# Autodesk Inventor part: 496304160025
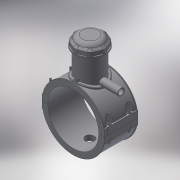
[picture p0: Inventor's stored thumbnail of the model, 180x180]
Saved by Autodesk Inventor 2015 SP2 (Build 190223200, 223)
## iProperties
Created: 2017-07
Part Number: 496304160025
Material: Generic
Description: PLASSON TAPPING SADDLE 160x25
Document SubType Name: Modeling
Designer: KIM
Mass: 1390.11 g
Surface Area: 2382.65 cm^2
Volume: 1390.11 cm^3
Density: 1 g/cm^3
Appearance: Default
Author: KIM
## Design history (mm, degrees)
derived "496304.ipt"
feature "Solid1::496304.ipt"
feature "Solid2::496304.ipt"
feature "Solid4::496304.ipt"
feature "Solid5::496304.ipt"
tag "TaggingFeature1"
body "Solid1"
body "Solid2"
other parameters: "B_" = 199, "L_" = 118, "d_t" = 6, "H_2" = 138, "H_1" = 21, "d_1" = 25, "d1" = 192, "d148" = 2.4, "d160" = 2.4, "d169" = 3.375, "d192" = 6.3, "d2" = 199, "d4" = 118, "d5" = 0, "d6" = 0.1, "d8" = 0, "d19" = 6, "d20" = 6, "d21" = 70.8, "d23" = 0, "d24" = 35.4, "d26" = 0, "d29" = 3, "d30" = 53.33333, "d31" = 6, "d32" = 0, "d33" = 0, "d34" = 0.6, "d40" = 99.84, "d41" = 96, "d43" = 0, "d45" = 0, "d47" = 166.8, "d70" = 15, "d72" = 0, "d73" = 6, "d75" = 5, "d76" = 0, "d77" = 8, "d79" = 15, "d80" = 47.2, "d82" = 5 deg, "d84" = 4, "d85" = 14, "d86" = 0, "d87" = 3, "d88" = 0, "d89" = 1, "d90" = 1, "d91" = 94.4, "d92" = 0, "d93" = 0.5, "d94" = 84.21053, "d96" = 195.84, "d97" = 2.36, "d98" = 0, "d102" = 1.6, "d120" = 140 deg, "d121" = 24.228, "d122" = 20 deg, "d123" = 384, "d124" = 115.2, "d126" = 0, "d143" = 164.8, "d145" = 24.61538, "d149" = 2.4, "d150" = 27.07692, "d153" = 118, "d154" = 0, "d156" = 96, "d157" = 160 deg, "d159" = 6.4, "d161" = 2.4, "d162" = 70.8, "d163" = 0, "d167" = 16, "d168" = 93.65854, "d170" = 3.375, "d172" = 0, "d173" = 1, "d176" = 20 deg, "d177" = 11.2, "d178" = 32, "d180" = 0, "d183" = 12.8, "d184" = 8.96, "d185" = 38.35, "d186" = 38.35, "d187" = 96, "d188" = 9.6, "d189" = 11.2, "d190" = 0, "d191" = 144, "d193" = 6.3, "d194" = 4.13, "d195" = 90 deg, "d197" = 0, "d199" = 0, "d200" = 16, "d202" = 0, "d203" = 138, "d204" = 91.2, "d205" = 67.2, "d206" = 81.6, "d207" = 103.5, "d208" = 107.64, "d209" = 128.34, "d210" = 82.56, "d211" = 96, "d212" = 76.8, "d213" = 7.65, "d216" = 0, "d217" = 16, "d218" = 16, "d219" = 3.2, "d224" = 0, "d230" = 6.4, "d233" = 6, "d236" = 99.5, "d237" = 35.4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
